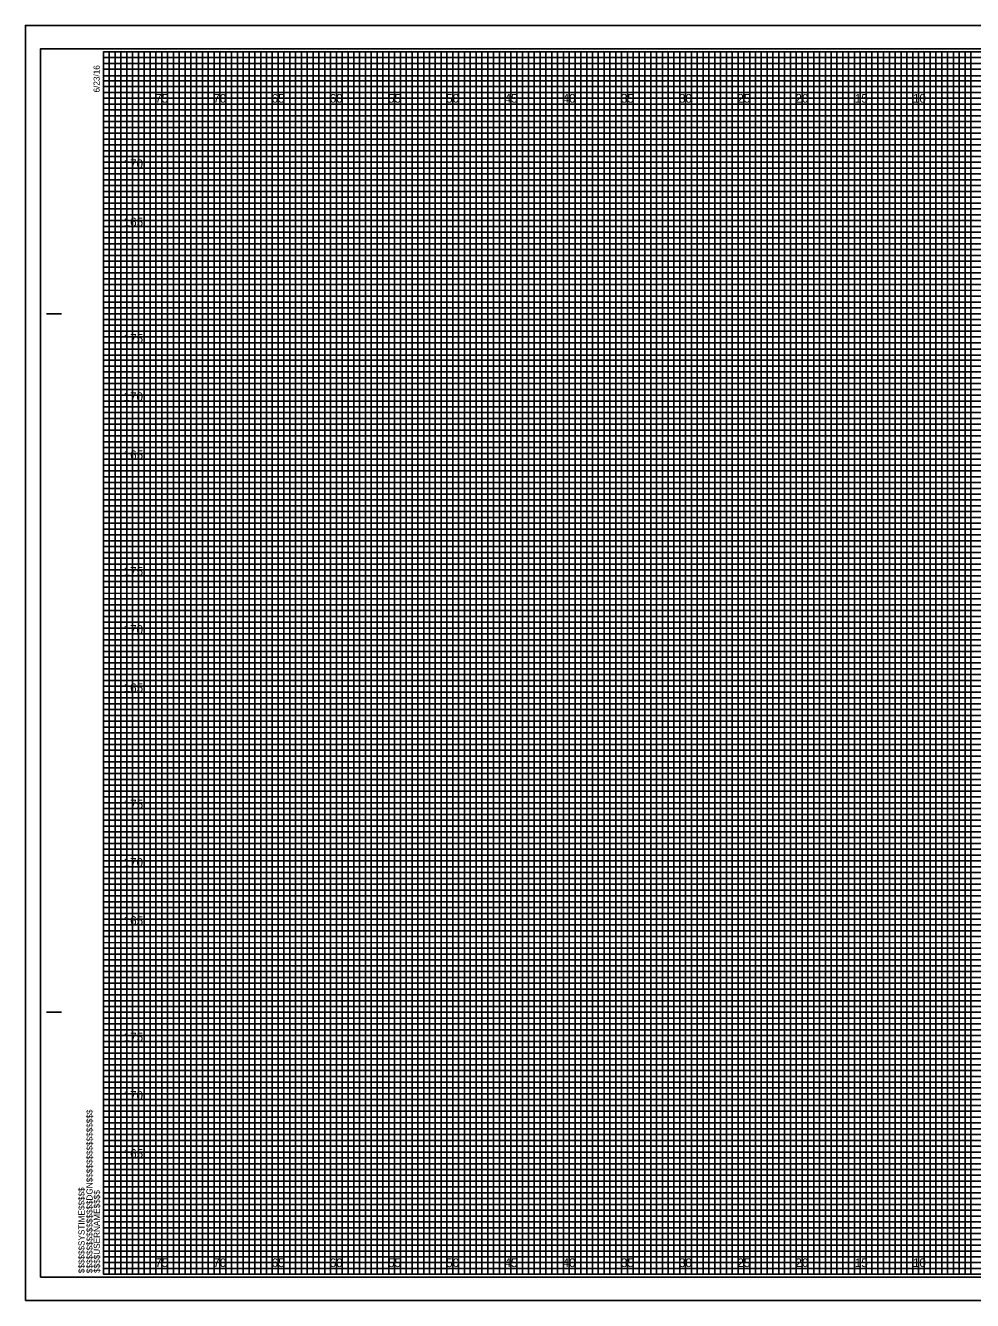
# Model space of a CAD drawing. Extents: x -7 to 162, y 108 to 217.
# Drawn here: x -6.7 to 74.6, y 107.7 to 217.2 of the extents above; entities that cross this region are included whole.
import ezdxf

# ---------------------------------------------------------------- set-up
doc = ezdxf.new("R2010")
doc.units = 0
for name, color, linetype in [('Exist Cross Section Cell', 7, 'Continuous'), ('Exist XS Center Line Elevation Label', 7, 'Continuous'), ('Exist XS Ground Line', 7, 'Continuous'), ('Prop CMT Conc Surface', 7, 'Continuous'), ('Prop CMT Concrete Structures', 7, 'Continuous'), ('Prop CMT Pvmt Course 1', 7, 'Continuous'), ('Prop CMT Pvmt Course 2', 7, 'Continuous'), ('Prop CMT Pvmt Course 3', 7, 'Continuous'), ('Prop CMT Slope Grass', 7, 'Continuous'), ('Prop CMT Subgrade Earthwork', 7, 'Continuous'), ('Scratch_Level_0', 7, 'Continuous')]:
    doc.layers.add(name, color=color, linetype=linetype)

msp = doc.modelspace()

# ---------------------------------------------------------------- linework, layer by layer
at = {"layer": 'Exist XS Center Line Elevation Label'}
for points in [[(0, 215), (2.5, 215), (2.5, 110), (7.5, 110), (7.5, 215), (12.5, 215), (12.5, 110), (17.5, 110), (17.5, 215), (22.5, 215), (22.5, 110), (27.5, 110), (27.5, 215), (32.5, 215), (32.5, 110), (37.5, 110), (37.5, 215), (42.5, 215), (42.5, 110), (47.5, 110), (47.5, 215), (52.5, 215), (52.5, 110), (57.5, 110), (57.5, 215), (62.5, 215), (62.5, 110), (67.5, 110), (67.5, 215), (72.5, 215), (72.5, 110), (77.5, 110)], [(0, 212.5), (137.5, 212.5)], [(0, 202.5), (160, 202.5), (160, 207.5), (0, 207.5)], [(0, 192.5), (160, 192.5), (160, 197.5), (0, 197.5)], [(0, 182.5), (160, 182.5), (160, 187.5), (0, 187.5)], [(0, 172.5), (160, 172.5), (160, 177.5), (0, 177.5)], [(0, 162.5), (160, 162.5), (160, 167.5), (0, 167.5)], [(0, 152.5), (160, 152.5), (160, 157.5), (0, 157.5)], [(0, 142.5), (160, 142.5), (160, 147.5), (0, 147.5)], [(0, 132.5), (160, 132.5), (160, 137.5), (0, 137.5)], [(0, 122.5), (160, 122.5), (160, 127.5), (0, 127.5)], [(0, 112.5), (160, 112.5), (160, 117.5), (0, 117.5)]]:
    msp.add_lwpolyline(points, dxfattribs=at)
at = {"layer": 'Exist XS Ground Line'}
for p, q in [((5, 215), (0, 215)), ((5, 110), (5, 215)), ((15, 215), (10, 215)), ((10, 215), (10, 110)), ((15, 110), (15, 215)), ((25, 215), (20, 215)), ((20, 215), (20, 110)), ((25, 110), (25, 215)), ((35, 215), (30, 215)), ((30, 215), (30, 110)), ((35, 110), (35, 215)), ((45, 215), (40, 215)), ((40, 215), (40, 110)), ((45, 110), (45, 215)), ((55, 215), (50, 215)), ((50, 215), (50, 110)), ((55, 110), (55, 215)), ((65, 215), (60, 215)), ((60, 215), (60, 110)), ((65, 110), (65, 215)), ((75, 215), (70, 215)), ((70, 215), (70, 110)), ((10, 110), (5, 110)), ((20, 110), (15, 110)), ((30, 110), (25, 110)), ((40, 110), (35, 110)), ((50, 110), (45, 110)), ((60, 110), (55, 110)), ((70, 110), (65, 110))]:
    msp.add_line(p, q, dxfattribs=at)
for points in [[(0, 210), (160, 210), (160, 205), (0, 205)], [(0, 200), (160, 200), (160, 195), (0, 195)], [(0, 190), (160, 190), (160, 185), (0, 185)], [(0, 180), (160, 180), (160, 175), (0, 175)], [(0, 170), (160, 170), (160, 165), (0, 165)], [(0, 160), (160, 160), (160, 155), (0, 155)], [(0, 150), (160, 150), (160, 145), (0, 145)], [(0, 140), (160, 140), (160, 135), (0, 135)], [(0, 130), (160, 130), (160, 125), (0, 125)], [(0, 120), (160, 120), (160, 115), (0, 115)]]:
    msp.add_lwpolyline(points, dxfattribs=at)
at = {"layer": 'Prop CMT Conc Surface'}
for p, q in [((5, 110), (5, 215)), ((10, 110), (10, 215)), ((15, 110), (15, 215)), ((20, 110), (20, 215)), ((25, 110), (25, 215)), ((30, 110), (30, 215)), ((35, 110), (35, 215)), ((40, 110), (40, 215)), ((45, 110), (45, 215)), ((50, 110), (50, 215)), ((55, 110), (55, 215)), ((60, 110), (60, 215)), ((65, 110), (65, 215)), ((70, 110), (70, 215)), ((0, 210), (160, 210)), ((0, 205), (160, 205)), ((0, 200), (160, 200)), ((0, 195), (160, 195)), ((0, 190), (160, 190)), ((0, 185), (160, 185)), ((0, 180), (160, 180)), ((0, 175), (160, 175)), ((0, 170), (160, 170)), ((0, 165), (160, 165)), ((0, 160), (160, 160)), ((0, 155), (160, 155)), ((0, 150), (160, 150)), ((0, 145), (160, 145)), ((0, 140), (160, 140)), ((0, 135), (160, 135)), ((0, 130), (160, 130)), ((0, 125), (160, 125)), ((0, 120), (160, 120)), ((0, 115), (160, 115))]:
    msp.add_line(p, q, dxfattribs=at)
at = {"layer": 'Prop CMT Pvmt Course 1'}
for points in [[(0, 110), (0.5, 110), (0.5, 215), (1, 215), (1, 110)], [(1, 110), (1.5, 110), (1.5, 215), (2, 215), (2, 110)], [(2.5, 110), (3, 110), (3, 215), (3.5, 215), (3.5, 110)], [(3.5, 110), (4, 110), (4, 215), (4.5, 215), (4.5, 110)], [(5, 110), (5.5, 110), (5.5, 215), (6, 215), (6, 110)], [(6, 110), (6.5, 110), (6.5, 215), (7, 215), (7, 110)], [(7.5, 110), (8, 110), (8, 215), (8.5, 215), (8.5, 110)], [(8.5, 110), (9, 110), (9, 215), (9.5, 215), (9.5, 110)], [(10, 110), (10.5, 110), (10.5, 215), (11, 215), (11, 110)], [(11, 110), (11.5, 110), (11.5, 215), (12, 215), (12, 110)], [(12.5, 110), (13, 110), (13, 215), (13.5, 215), (13.5, 110)], [(13.5, 110), (14, 110), (14, 215), (14.5, 215), (14.5, 110)], [(15, 110), (15.5, 110), (15.5, 215), (16, 215), (16, 110)], [(16, 110), (16.5, 110), (16.5, 215), (17, 215), (17, 110)], [(17.5, 110), (18, 110), (18, 215), (18.5, 215), (18.5, 110)], [(18.5, 110), (19, 110), (19, 215), (19.5, 215), (19.5, 110)], [(20, 110), (20.5, 110), (20.5, 215), (21, 215), (21, 110)], [(21, 110), (21.5, 110), (21.5, 215), (22, 215), (22, 110)], [(22.5, 110), (23, 110), (23, 215), (23.5, 215), (23.5, 110)], [(23.5, 110), (24, 110), (24, 215), (24.5, 215), (24.5, 110)], [(25, 110), (25.5, 110), (25.5, 215), (26, 215), (26, 110)], [(26, 110), (26.5, 110), (26.5, 215), (27, 215), (27, 110)], [(27.5, 110), (28, 110), (28, 215), (28.5, 215), (28.5, 110)], [(28.5, 110), (29, 110), (29, 215), (29.5, 215), (29.5, 110)], [(30, 110), (30.5, 110), (30.5, 215), (31, 215), (31, 110)], [(31, 110), (31.5, 110), (31.5, 215), (32, 215), (32, 110)], [(32.5, 110), (33, 110), (33, 215), (33.5, 215), (33.5, 110)], [(33.5, 110), (34, 110), (34, 215), (34.5, 215), (34.5, 110)], [(35, 110), (35.5, 110), (35.5, 215), (36, 215), (36, 110)], [(36, 110), (36.5, 110), (36.5, 215), (37, 215), (37, 110)], [(37.5, 110), (38, 110), (38, 215), (38.5, 215), (38.5, 110)], [(38.5, 110), (39, 110), (39, 215), (39.5, 215), (39.5, 110)], [(40, 110), (40.5, 110), (40.5, 215), (41, 215), (41, 110)], [(41, 110), (41.5, 110), (41.5, 215), (42, 215), (42, 110)], [(42.5, 110), (43, 110), (43, 215), (43.5, 215), (43.5, 110)], [(43.5, 110), (44, 110), (44, 215), (44.5, 215), (44.5, 110)], [(45, 110), (45.5, 110), (45.5, 215), (46, 215), (46, 110)], [(46, 110), (46.5, 110), (46.5, 215), (47, 215), (47, 110)], [(47.5, 110), (48, 110), (48, 215), (48.5, 215), (48.5, 110)], [(48.5, 110), (49, 110), (49, 215), (49.5, 215), (49.5, 110)], [(50, 110), (50.5, 110), (50.5, 215), (51, 215), (51, 110)], [(51, 110), (51.5, 110), (51.5, 215), (52, 215), (52, 110)], [(52.5, 110), (53, 110), (53, 215), (53.5, 215), (53.5, 110)], [(53.5, 110), (54, 110), (54, 215), (54.5, 215), (54.5, 110)], [(55, 110), (55.5, 110), (55.5, 215), (56, 215), (56, 110)], [(56, 110), (56.5, 110), (56.5, 215), (57, 215), (57, 110)], [(57.5, 110), (58, 110), (58, 215), (58.5, 215), (58.5, 110)], [(58.5, 110), (59, 110), (59, 215), (59.5, 215), (59.5, 110)], [(60, 110), (60.5, 110), (60.5, 215), (61, 215), (61, 110)], [(61, 110), (61.5, 110), (61.5, 215), (62, 215), (62, 110)], [(62.5, 110), (63, 110), (63, 215), (63.5, 215), (63.5, 110)], [(63.5, 110), (64, 110), (64, 215), (64.5, 215), (64.5, 110)], [(65, 110), (65.5, 110), (65.5, 215), (66, 215), (66, 110)], [(66, 110), (66.5, 110), (66.5, 215), (67, 215), (67, 110)], [(67.5, 110), (68, 110), (68, 215), (68.5, 215), (68.5, 110)], [(68.5, 110), (69, 110), (69, 215), (69.5, 215), (69.5, 110)], [(70, 110), (70.5, 110), (70.5, 215), (71, 215), (71, 110)], [(71, 110), (71.5, 110), (71.5, 215), (72, 215), (72, 110)], [(72.5, 110), (73, 110), (73, 215), (73.5, 215), (73.5, 110)], [(73.5, 110), (74, 110), (74, 215), (74.5, 215), (74.5, 110)]]:
    msp.add_lwpolyline(points, dxfattribs=at)
at = {"layer": 'Prop CMT Pvmt Course 2'}
msp.add_lwpolyline([(-6.7, 107.75), (161.65, 107.75), (161.65, 217.25), (-6.7, 217.25)], close=True, dxfattribs=at)
at = {"layer": 'Prop CMT Pvmt Course 3'}
msp.add_lwpolyline([(-5.4, 109.75), (161.2, 109.75), (161.2, 215.25), (-5.4, 215.25)], close=True, dxfattribs=at)
at = {"layer": 'Prop CMT Slope Grass'}
for p, q in [((161.65, 217.25), (-6.7, 217.25)), ((-6.7, 217.25), (-6.7, 107.75)), ((-6.7, 107.75), (161.65, 107.75))]:
    msp.add_line(p, q, dxfattribs=at)
at = {"layer": 'Prop CMT Subgrade Earthwork'}
for p, q in [((-4.9, 192.5), (-3.65, 192.5)), ((-4.85, 192.5), (-3.6, 192.5)), ((-4.9, 132.5), (-3.65, 132.5)), ((-4.85, 132.5), (-3.6, 132.5)), ((0, 110), (0, 110)), ((0, 110), (0, 110)), ((0, 110), (0, 110)), ((0, 110), (0, 110)), ((0, 110), (0, 110)), ((0, 110), (0, 110)), ((0, 110), (0, 110))]:
    msp.add_line(p, q, dxfattribs=at)
msp.add_lwpolyline([(160, 215), (0, 215), (0, 110), (160, 110)], close=True, dxfattribs=at)
at = {"layer": 'Scratch_Level_0'}
for p, q in [((0, 214.5), (130, 214.5)), ((130, 213.99), (0, 213.99)), ((0, 213.99), (0, 213.5)), ((0, 213.5), (130, 213.5)), ((130, 212.94), (0, 212.94)), ((0, 212.94), (0, 212)), ((0, 212), (160, 212))]:
    msp.add_line(p, q, dxfattribs=at)
for points in [[(0, 211.5), (135, 211.5), (160, 211.5), (160, 211), (0, 211)], [(0, 210.5), (160, 210.5), (160, 209.5), (0, 209.5)], [(0, 209), (160, 209), (160, 208.5), (0, 208.49)], [(0, 208), (160, 208), (160, 207), (0, 207)], [(0, 206.5), (160, 206.5), (160, 206), (0, 206)], [(0, 205.5), (160, 205.5), (160, 204.5), (0, 204.5)], [(0, 204), (160, 204), (160, 203.5), (0, 203.5)], [(0, 203), (160, 203), (160, 202), (0, 202)], [(0, 201.5), (160, 201.5), (160, 201), (0, 201)], [(0, 200.5), (160, 200.5), (160, 199.5), (0, 199.5)], [(0, 199), (160, 199), (160, 198.5), (0, 198.5)], [(0, 198), (160, 198), (160, 196.97), (160, 196.5), (160, 196), (0, 196)], [(0, 197), (160, 197), (160, 196.5), (0, 196.5)], [(0, 195.5), (160, 195.5), (160, 194.5), (0, 194.52)], [(0, 194.52), (160, 194.5), (160, 194), (0, 194)], [(0, 193.5), (160, 193.5), (160, 193), (0, 193)], [(0, 192), (160, 192), (160, 191.5), (0, 191.5)], [(0, 191), (160, 191), (160, 190.5), (0, 190.5)], [(-0.04, 189.44), (160, 189.44), (160, 188.94), (-0.04, 188.94)], [(0, 188.5), (160, 188.5), (160, 188), (0, 188)], [(0, 187), (160, 187), (160, 186.5), (0, 186.5)], [(0, 186), (160, 186), (160, 185.5), (0, 185.5)], [(0, 184.5), (160, 184.5), (160, 184), (0, 184)], [(0, 183.5), (160, 183.5), (160, 183), (0, 183)], [(0, 182), (160, 182), (160, 181.5), (0, 181.5)], [(0, 181), (160, 181), (160, 180.5), (0, 180.5)], [(0, 179.5), (160, 179.5), (160, 178.99), (0, 179)], [(0, 178.5), (160, 178.5), (160, 178), (0, 178)], [(0, 177), (160, 177), (160, 176.5), (0, 176.5)], [(0, 176), (160, 176), (160, 175.5), (0, 175.5)], [(0, 174.5), (160, 174.5), (160, 174), (0, 174)], [(0, 173.5), (160, 173.5), (160, 173), (0, 173)], [(0, 172), (160, 172), (160, 171.5), (0, 171.5)], [(0, 171), (160, 171), (160, 170.5), (0, 170.5)], [(0, 169.5), (160, 169.5), (160, 169), (0, 169)], [(0, 168.5), (160.03, 168.46), (160, 168), (0, 168)], [(0, 167), (160, 167), (160, 166.5), (0, 166.5)], [(0, 166), (160, 166), (160, 165.5), (0, 165.5)], [(0, 164.5), (160, 164.5), (160, 164), (0, 164)], [(0, 163.5), (160, 163.5), (160, 163), (0, 163)], [(0, 162), (160, 162), (160, 161.5), (0, 161.5)], [(0, 161), (160, 161), (160, 160.5), (0, 160.5)], [(0, 159.5), (160, 159.5), (160, 159), (0, 159)], [(0, 158.5), (160, 158.5), (160, 158), (0, 158)], [(0, 157), (160, 157), (160, 156.5), (0, 156.5)], [(0, 156), (160, 156), (160, 155.5), (0, 155.5)], [(0, 154.5), (160, 154.5), (160, 154), (0, 154)], [(0, 153.5), (160, 153.5), (160, 153), (0, 153)], [(0, 152), (160, 152), (160, 151.5), (0, 151.5)], [(0, 151), (160, 151), (160, 150.5), (0, 150.5)], [(0, 149.5), (160, 149.5), (160, 148.99), (0, 149)], [(0, 148.5), (160, 148.5), (160, 148), (0, 148)], [(0, 147), (160, 147), (160, 146.5), (0, 146.5)], [(0, 146), (160, 146), (160, 145.5), (0, 145.5)], [(0, 144.5), (160, 144.5), (160, 144), (0, 144)], [(0, 143.5), (160, 143.5), (160, 143), (0, 143)], [(0, 142), (160, 142), (160, 141.5), (0, 141.5)], [(0, 141), (160, 141), (160, 140.5), (0, 140.5)], [(0, 139.5), (160, 139.5), (160, 139), (0, 139)], [(0, 138.5), (160.03, 138.46), (160, 138), (0, 138)], [(0, 137), (160, 137), (160, 136.5), (0, 136.5)], [(0, 136), (160, 136), (160, 135.5), (0, 135.5)], [(0, 134.5), (160, 134.5), (160, 134), (0, 134)], [(0, 133.5), (160, 133.5), (160, 133), (0, 133)], [(0, 132), (160, 132), (160, 131.5), (0, 131.5)], [(0, 131), (160, 131), (160, 130.5), (0, 130.5)], [(0, 129.5), (160, 129.5), (160, 129), (0, 129)], [(0, 128.5), (160, 128.5), (160, 128), (0, 128)], [(0, 127), (160, 127), (160, 126.5), (0, 126.5)], [(0, 126), (160, 126), (160, 125.5), (0, 125.5)], [(0, 124.5), (160, 124.5), (160, 124), (0, 124)], [(0, 123.5), (160, 123.5), (160, 123), (0, 123)], [(0, 122), (160, 122), (160, 121.5), (0, 121.5)], [(0, 121), (160, 121), (160, 120.5), (0, 120.5)], [(0, 119.5), (160, 119.5), (160, 119), (0, 119)], [(0, 118.5), (160, 118.5), (160, 118), (0, 118)], [(0, 117), (160, 117), (160, 116.5), (0, 116.5)], [(0, 116), (160, 116), (160, 115.5), (0, 115.5)], [(0, 114.5), (160, 114.5), (160, 114), (0, 114)], [(0, 113.5), (160, 113.5), (160, 113), (0, 113)], [(0, 112), (160, 112), (160, 111.5), (0, 111.5)], [(0, 111), (160, 111), (160, 110.5), (0, 110.5)]]:
    msp.add_lwpolyline(points, dxfattribs=at)

# ---------------------------------------------------------------- texts
at = {"layer": 'Exist Cross Section Cell'}
for s, p in [('75', (4.44, 210.62)), ('70', (9.43, 210.62)), ('65', (14.44, 210.62)), ('60', (19.43, 210.62)), ('55', (24.44, 210.62)), ('50', (29.43, 210.62)), ('45', (34.44, 210.62)), ('40', (39.43, 210.62)), ('35', (44.44, 210.62)), ('30', (49.43, 210.62)), ('25', (54.44, 210.62)), ('20', (59.43, 210.62)), ('15', (64.53, 210.62)), ('10', (69.52, 210.62)), ('75', (4.44, 110.62)), ('70', (9.43, 110.62)), ('65', (14.44, 110.62)), ('60', (19.43, 110.62)), ('55', (24.44, 110.62)), ('50', (29.43, 110.62)), ('45', (34.44, 110.62)), ('40', (39.43, 110.62)), ('35', (44.44, 110.62)), ('30', (49.43, 110.62)), ('25', (54.44, 110.62)), ('20', (59.43, 110.62)), ('15', (64.53, 110.62)), ('10', (69.52, 110.62))]:
    msp.add_text(s, height=0.75, dxfattribs=at).set_placement(p)
at = {"layer": 'Prop CMT Concrete Structures'}
for s, p in [('170', (1.72, 205)), ('165', (1.73, 200)), ('175', (1.73, 190)), ('170', (1.72, 185)), ('165', (1.73, 180)), ('175', (1.73, 170)), ('170', (1.72, 165)), ('165', (1.73, 160)), ('175', (1.73, 150)), ('170', (1.72, 145)), ('165', (1.73, 140)), ('175', (1.73, 130)), ('170', (1.72, 125)), ('165', (1.73, 120))]:
    msp.add_text(s, height=0.75, dxfattribs=at).set_placement(p)
at = {"layer": 'Prop CMT Subgrade Earthwork'}
for s, p in [('6/23/16', (-0.33, 211.5)), ('$$$$$$$$$$$$$$$$DGN$$$$$$$$$$$$$$$$', (-0.94, 110.09)), ('$$$$$$SYSTIME$$$$$', (-1.63, 110.09)), ('$$$$USERNAME$$$$', (-0.31, 110.12))]:
    msp.add_text(s, height=0.525, rotation=90, dxfattribs=at).set_placement(p)

doc.saveas('drawing.dxf')
